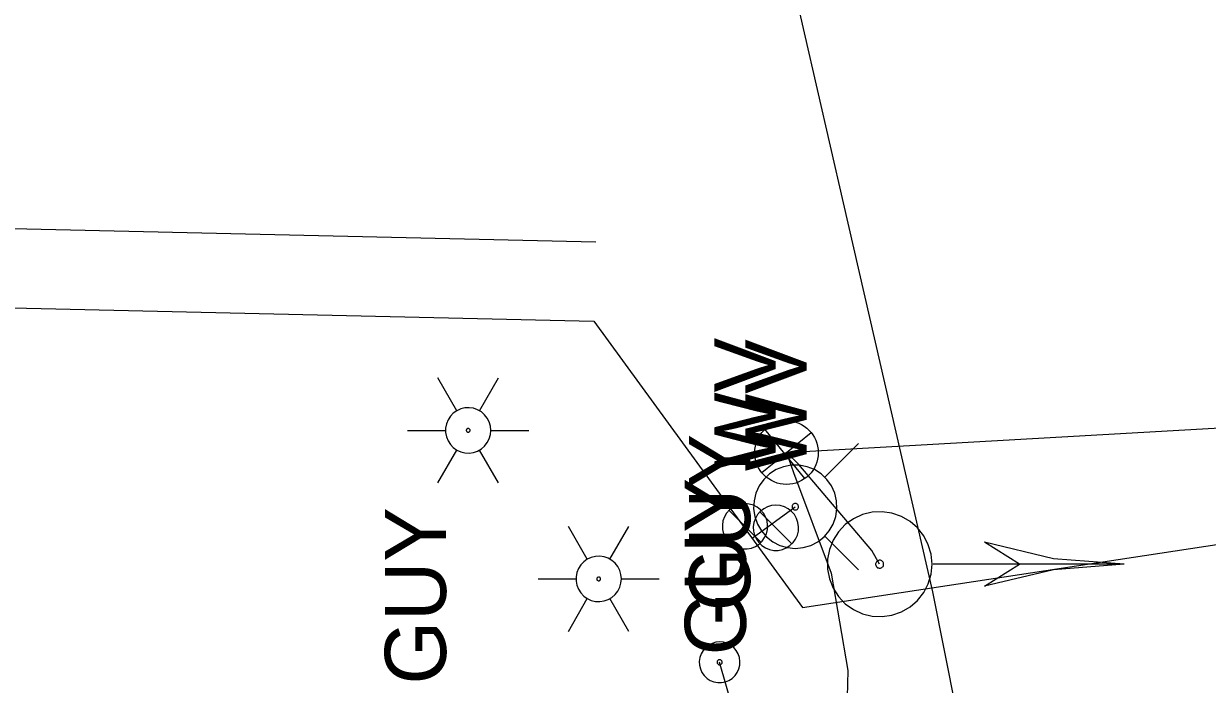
# Model space of a CAD drawing. Extents: x 596028 to 606371, y 330010 to 403088.
# Drawn here: x 604637.5 to 604712, y 339438.6 to 339480.1 of the extents above; entities that cross this region are included whole.
import ezdxf

# ---------------------------------------------------------------- set-up
doc = ezdxf.new("R2010")
doc.units = 0
for name, color, linetype in [('E_LTG', 7, 'Continuous'), ('E_SIG', 7, 'Continuous'), ('E_SIG_Conduit', 7, 'Continuous'), ('E_UTL_E_UG', 7, 'Continuous'), ('E_UTL_EGuyWire', 7, 'Continuous'), ('E_UTL_FO_UG', 7, 'Continuous'), ('E_UTL_G_UG', 7, 'Continuous'), ('E_UTL_W', 7, 'Continuous'), ('E_UTL_W_UG', 7, 'Continuous'), ('E_UTL_WHydrant', 7, 'Continuous')]:
    doc.layers.add(name, color=color, linetype=linetype)

# ---------------------------------------------------------------- blocks, each defined once
blk = doc.blocks.new('_U332')
at = {"layer": 'E_SIG'}
for p, q in [((0, 6.1), (0, -6.1)), ((-6.09, 0.4), (6.1, 0.4))]:
    blk.add_line(p, q, dxfattribs=at)
blk.add_circle((0, 0.01), 6.1, dxfattribs=at)

msp = doc.modelspace()

# ---------------------------------------------------------------- linework, layer by layer
at = {"layer": 'E_LTG'}
for points in [[(604664.786, 339455.777), (604663.595, 339457.839)], [(604666.214, 339455.777), (604667.405, 339457.839)], [(604666.929, 339454.539), (604666.903, 339454.809), (604666.827, 339455.07), (604666.702, 339455.312), (604666.534, 339455.525), (604666.329, 339455.703), (604666.094, 339455.839), (604665.837, 339455.928), (604665.568, 339455.966), (604665.297, 339455.953), (604665.033, 339455.889), (604664.786, 339455.777), (604664.564, 339455.619), (604664.377, 339455.422), (604664.23, 339455.194), (604664.129, 339454.942), (604664.077, 339454.675), (604664.077, 339454.403), (604664.129, 339454.136), (604664.23, 339453.884), (604664.377, 339453.656), (604664.564, 339453.459), (604664.786, 339453.301), (604665.033, 339453.189), (604665.297, 339453.125), (604665.568, 339453.112), (604665.837, 339453.15), (604666.094, 339453.239), (604666.329, 339453.375), (604666.534, 339453.553), (604666.702, 339453.766), (604666.827, 339454.008), (604666.903, 339454.269), (604666.929, 339454.539)], [(604666.929, 339454.539), (604666.903, 339454.809), (604666.827, 339455.07), (604666.702, 339455.312), (604666.534, 339455.525), (604666.329, 339455.703), (604666.094, 339455.839), (604665.837, 339455.928), (604665.568, 339455.966), (604665.297, 339455.953), (604665.033, 339455.889), (604664.786, 339455.777), (604664.564, 339455.619), (604664.377, 339455.422), (604664.23, 339455.194), (604664.129, 339454.942), (604664.077, 339454.675), (604664.077, 339454.403), (604664.129, 339454.136), (604664.23, 339453.884), (604664.377, 339453.656), (604664.564, 339453.459), (604664.786, 339453.301), (604665.033, 339453.189), (604665.297, 339453.125), (604665.568, 339453.112), (604665.837, 339453.15), (604666.094, 339453.239), (604666.329, 339453.375), (604666.534, 339453.553), (604666.702, 339453.766), (604666.827, 339454.008), (604666.903, 339454.269), (604666.929, 339454.539)], [(604666.929, 339454.539), (604666.903, 339454.809), (604666.827, 339455.07), (604666.702, 339455.312), (604666.534, 339455.525), (604666.329, 339455.703), (604666.094, 339455.839), (604665.837, 339455.928), (604665.568, 339455.966), (604665.297, 339455.953), (604665.033, 339455.889), (604664.786, 339455.777), (604664.564, 339455.619), (604664.377, 339455.422), (604664.23, 339455.194), (604664.129, 339454.942), (604664.077, 339454.675), (604664.077, 339454.403), (604664.129, 339454.136), (604664.23, 339453.884), (604664.377, 339453.656), (604664.564, 339453.459), (604664.786, 339453.301), (604665.033, 339453.189), (604665.297, 339453.125), (604665.568, 339453.112), (604665.837, 339453.15), (604666.094, 339453.239), (604666.329, 339453.375), (604666.534, 339453.553), (604666.702, 339453.766), (604666.827, 339454.008), (604666.903, 339454.269), (604666.929, 339454.539)], [(604661.689, 339454.539), (604664.071, 339454.539)], [(604665.619, 339454.539), (604665.617, 339454.562), (604665.611, 339454.583), (604665.6, 339454.603), (604665.586, 339454.621), (604665.569, 339454.636), (604665.549, 339454.647), (604665.528, 339454.655), (604665.506, 339454.658), (604665.483, 339454.657), (604665.461, 339454.652), (604665.44, 339454.642), (604665.422, 339454.629), (604665.406, 339454.613), (604665.394, 339454.594), (604665.386, 339454.573), (604665.381, 339454.55), (604665.381, 339454.528), (604665.386, 339454.505), (604665.394, 339454.484), (604665.406, 339454.465), (604665.422, 339454.449), (604665.44, 339454.436), (604665.461, 339454.426), (604665.483, 339454.421), (604665.506, 339454.42), (604665.528, 339454.423), (604665.549, 339454.431), (604665.569, 339454.442), (604665.586, 339454.457), (604665.6, 339454.475), (604665.611, 339454.495), (604665.617, 339454.516), (604665.619, 339454.539)], [(604666.929, 339454.539), (604669.311, 339454.539)], [(604663.595, 339451.239), (604664.786, 339453.302)], [(604667.405, 339451.239), (604666.214, 339453.302)], [(604672.999, 339446.435), (604671.808, 339448.497)], [(604674.427, 339446.435), (604675.618, 339448.497)], [(604675.142, 339445.197), (604675.116, 339445.467), (604675.04, 339445.728), (604674.915, 339445.97), (604674.747, 339446.183), (604674.542, 339446.361), (604674.307, 339446.497), (604674.05, 339446.586), (604673.781, 339446.624), (604673.51, 339446.611), (604673.246, 339446.547), (604672.999, 339446.435), (604672.777, 339446.277), (604672.59, 339446.08), (604672.443, 339445.852), (604672.342, 339445.6), (604672.29, 339445.333), (604672.29, 339445.061), (604672.342, 339444.794), (604672.443, 339444.542), (604672.59, 339444.314), (604672.777, 339444.117), (604672.999, 339443.959), (604673.246, 339443.847), (604673.51, 339443.783), (604673.781, 339443.77), (604674.05, 339443.808), (604674.307, 339443.897), (604674.542, 339444.033), (604674.747, 339444.211), (604674.915, 339444.424), (604675.04, 339444.666), (604675.116, 339444.927), (604675.142, 339445.197)], [(604675.142, 339445.197), (604675.116, 339445.467), (604675.04, 339445.728), (604674.915, 339445.97), (604674.747, 339446.183), (604674.542, 339446.361), (604674.307, 339446.497), (604674.05, 339446.586), (604673.781, 339446.624), (604673.51, 339446.611), (604673.246, 339446.547), (604672.999, 339446.435), (604672.777, 339446.277), (604672.59, 339446.08), (604672.443, 339445.852), (604672.342, 339445.6), (604672.29, 339445.333), (604672.29, 339445.061), (604672.342, 339444.794), (604672.443, 339444.542), (604672.59, 339444.314), (604672.777, 339444.117), (604672.999, 339443.959), (604673.246, 339443.847), (604673.51, 339443.783), (604673.781, 339443.77), (604674.05, 339443.808), (604674.307, 339443.897), (604674.542, 339444.033), (604674.747, 339444.211), (604674.915, 339444.424), (604675.04, 339444.666), (604675.116, 339444.927), (604675.142, 339445.197)], [(604675.142, 339445.197), (604675.116, 339445.467), (604675.04, 339445.728), (604674.915, 339445.97), (604674.747, 339446.183), (604674.542, 339446.361), (604674.307, 339446.497), (604674.05, 339446.586), (604673.781, 339446.624), (604673.51, 339446.611), (604673.246, 339446.547), (604672.999, 339446.435), (604672.777, 339446.277), (604672.59, 339446.08), (604672.443, 339445.852), (604672.342, 339445.6), (604672.29, 339445.333), (604672.29, 339445.061), (604672.342, 339444.794), (604672.443, 339444.542), (604672.59, 339444.314), (604672.777, 339444.117), (604672.999, 339443.959), (604673.246, 339443.847), (604673.51, 339443.783), (604673.781, 339443.77), (604674.05, 339443.808), (604674.307, 339443.897), (604674.542, 339444.033), (604674.747, 339444.211), (604674.915, 339444.424), (604675.04, 339444.666), (604675.116, 339444.927), (604675.142, 339445.197)], [(604669.902, 339445.197), (604672.284, 339445.197)], [(604673.832, 339445.197), (604673.83, 339445.22), (604673.824, 339445.241), (604673.813, 339445.261), (604673.799, 339445.279), (604673.782, 339445.294), (604673.762, 339445.305), (604673.741, 339445.313), (604673.719, 339445.316), (604673.696, 339445.315), (604673.674, 339445.31), (604673.653, 339445.3), (604673.635, 339445.287), (604673.619, 339445.271), (604673.607, 339445.252), (604673.599, 339445.231), (604673.594, 339445.208), (604673.594, 339445.186), (604673.599, 339445.163), (604673.607, 339445.142), (604673.619, 339445.123), (604673.635, 339445.107), (604673.653, 339445.094), (604673.674, 339445.084), (604673.696, 339445.079), (604673.719, 339445.078), (604673.741, 339445.081), (604673.762, 339445.089), (604673.782, 339445.1), (604673.799, 339445.115), (604673.813, 339445.133), (604673.824, 339445.153), (604673.83, 339445.174), (604673.832, 339445.197)], [(604675.142, 339445.197), (604677.524, 339445.197)], [(604671.808, 339441.897), (604672.999, 339443.96)], [(604675.618, 339441.897), (604674.427, 339443.96)]]:
    msp.add_lwpolyline(points, dxfattribs=at)
at = {"layer": 'E_SIG'}
for points in [[(604691.401, 339446.121), (604690.901, 339446.981), (604686.321, 339452.391), (604685.541, 339453.141)], [(604694.701, 339446.121), (604694.642, 339446.745), (604694.465, 339447.347), (604694.178, 339447.905), (604693.79, 339448.398), (604693.316, 339448.809), (604692.772, 339449.122), (604692.179, 339449.328), (604691.558, 339449.417), (604690.932, 339449.387), (604690.322, 339449.239), (604689.751, 339448.978), (604689.24, 339448.615), (604688.807, 339448.161), (604688.468, 339447.633), (604688.235, 339447.05), (604688.116, 339446.434), (604688.116, 339445.807), (604688.235, 339445.191), (604688.468, 339444.608), (604688.807, 339444.081), (604689.24, 339443.627), (604689.751, 339443.263), (604690.322, 339443.002), (604690.932, 339442.854), (604691.558, 339442.824), (604692.179, 339442.914), (604692.772, 339443.119), (604693.316, 339443.433), (604693.79, 339443.843), (604694.178, 339444.336), (604694.465, 339444.894), (604694.642, 339445.496), (604694.701, 339446.121)], [(604706.801, 339446.121), (604702.348, 339446.466), (604698.001, 339447.496)], [(604700.202, 339446.119), (604698.002, 339447.496)], [(604691.654, 339446.121), (604691.649, 339446.168), (604691.636, 339446.214), (604691.614, 339446.257), (604691.584, 339446.295), (604691.548, 339446.326), (604691.506, 339446.35), (604691.461, 339446.366), (604691.413, 339446.373), (604691.365, 339446.37), (604691.319, 339446.359), (604691.275, 339446.339), (604691.236, 339446.311), (604691.203, 339446.277), (604691.177, 339446.236), (604691.159, 339446.192), (604691.15, 339446.145), (604691.15, 339446.097), (604691.159, 339446.05), (604691.177, 339446.005), (604691.203, 339445.965), (604691.236, 339445.93), (604691.275, 339445.902), (604691.319, 339445.882), (604691.365, 339445.871), (604691.413, 339445.868), (604691.461, 339445.875), (604691.506, 339445.891), (604691.548, 339445.915), (604691.584, 339445.946), (604691.614, 339445.984), (604691.636, 339446.027), (604691.649, 339446.073), (604691.654, 339446.121)], [(604706.801, 339446.119), (604694.76, 339446.119)], [(604706.801, 339446.121), (604702.348, 339445.775), (604698.001, 339444.746)], [(604698.002, 339444.748), (604700.202, 339446.119)]]:
    msp.add_lwpolyline(points, dxfattribs=at)
at = {"layer": 'E_SIG_Conduit'}
for points in [[(604685.541, 339453.141), (604748.601, 339456.731)], [(604685.541, 339453.141), (604685.981, 339451.881), (604688.351, 339445.561), (604689.391, 339439.431), (604689.301, 339435.251), (604688.651, 339432.791)]]:
    msp.add_lwpolyline(points, dxfattribs=at)
at = {"layer": 'E_UTL_E_UG'}
msp.add_line((604541.191, 339469.419), (604673.529, 339466.399), dxfattribs=at)
at = {"layer": 'E_UTL_EGuyWire'}
msp.add_line((604683.979, 339430.78), (604681.327, 339439.949), dxfattribs=at)
for points in [[(604681.327, 339441.232), (604681.084, 339441.209), (604680.85, 339441.14), (604680.633, 339441.029), (604680.441, 339440.878), (604680.282, 339440.693), (604680.16, 339440.482), (604680.08, 339440.252), (604680.045, 339440.01), (604680.057, 339439.766), (604680.114, 339439.529), (604680.216, 339439.307), (604680.357, 339439.109), (604680.534, 339438.94), (604680.739, 339438.808), (604680.965, 339438.718), (604681.205, 339438.671), (604681.449, 339438.671), (604681.689, 339438.718), (604681.915, 339438.808), (604682.12, 339438.94), (604682.297, 339439.109), (604682.438, 339439.307), (604682.54, 339439.529), (604682.597, 339439.766), (604682.609, 339440.01), (604682.574, 339440.252), (604682.494, 339440.482), (604682.372, 339440.693), (604682.213, 339440.878), (604682.021, 339441.029), (604681.804, 339441.14), (604681.57, 339441.209), (604681.327, 339441.232)], [(604681.327, 339440.109), (604681.297, 339440.107), (604681.267, 339440.098), (604681.24, 339440.084), (604681.216, 339440.065), (604681.196, 339440.042), (604681.181, 339440.016), (604681.171, 339439.987), (604681.167, 339439.957), (604681.168, 339439.926), (604681.175, 339439.897), (604681.188, 339439.869), (604681.206, 339439.844), (604681.228, 339439.823), (604681.253, 339439.806), (604681.282, 339439.795), (604681.312, 339439.789), (604681.342, 339439.789), (604681.372, 339439.795), (604681.401, 339439.806), (604681.426, 339439.823), (604681.448, 339439.844), (604681.466, 339439.869), (604681.479, 339439.897), (604681.486, 339439.926), (604681.487, 339439.957), (604681.483, 339439.987), (604681.473, 339440.016), (604681.458, 339440.042), (604681.438, 339440.065), (604681.414, 339440.084), (604681.387, 339440.098), (604681.357, 339440.107), (604681.327, 339440.109)]]:
    msp.add_lwpolyline(points, dxfattribs=at)
at = {"layer": 'E_UTL_FO_UG'}
msp.add_lwpolyline([(604685.541, 339453.141), (604748.601, 339456.731), (604793.27, 339456.481)], dxfattribs=at)
at = {"layer": 'E_UTL_G_UG'}
msp.add_lwpolyline([(604742.351, 339228.682), (604740.051, 339238.172), (604732.171, 339281.151), (604723.131, 339319.311), (604718.151, 339342.271), (604709.951, 339377.231), (604705.891, 339396.141), (604699.951, 339418.231), (604694.751, 339444.391), (604689.121, 339468.851), (604685.031, 339486.701), (604684.681, 339487.291), (604678.371, 339490.441), (604676.201, 339500.021)], dxfattribs=at)
at = {"layer": 'E_UTL_W'}
for points in [[(604682.926, 339449.929), (604682.656, 339449.903), (604682.396, 339449.827), (604682.155, 339449.703), (604681.942, 339449.535), (604681.764, 339449.33), (604681.629, 339449.095), (604681.54, 339448.839), (604681.501, 339448.571), (604681.514, 339448.3), (604681.578, 339448.037), (604681.691, 339447.79), (604681.848, 339447.569), (604682.044, 339447.382), (604682.272, 339447.236), (604682.524, 339447.135), (604682.79, 339447.084), (604683.061, 339447.084), (604683.328, 339447.135), (604683.579, 339447.236), (604683.807, 339447.382), (604684.003, 339447.569), (604684.161, 339447.79), (604684.273, 339448.037), (604684.337, 339448.3), (604684.35, 339448.571), (604684.312, 339448.839), (604684.223, 339449.095), (604684.087, 339449.33), (604683.91, 339449.535), (604683.697, 339449.703), (604683.456, 339449.827), (604683.196, 339449.903), (604682.926, 339449.929)], [(604683.934, 339447.495), (604681.918, 339449.511)], [(604684.874, 339449.836), (604684.604, 339449.81), (604684.344, 339449.733), (604684.103, 339449.609), (604683.89, 339449.442), (604683.712, 339449.237), (604683.577, 339449.002), (604683.488, 339448.746), (604683.45, 339448.478), (604683.462, 339448.207), (604683.526, 339447.943), (604683.639, 339447.697), (604683.796, 339447.476), (604683.992, 339447.289), (604684.22, 339447.142), (604684.472, 339447.041), (604684.738, 339446.99), (604685.009, 339446.99), (604685.276, 339447.041), (604685.527, 339447.142), (604685.755, 339447.289), (604685.952, 339447.476), (604686.109, 339447.697), (604686.221, 339447.943), (604686.285, 339448.207), (604686.298, 339448.478), (604686.26, 339448.746), (604686.171, 339449.002), (604686.035, 339449.237), (604685.858, 339449.442), (604685.645, 339449.609), (604685.404, 339449.733), (604685.144, 339449.81), (604684.874, 339449.836)], [(604685.882, 339447.401), (604683.866, 339449.418)]]:
    msp.add_lwpolyline(points, dxfattribs=at)
at = {"layer": 'E_UTL_W_UG'}
for p, q in [((604536.91, 339464.515), (604673.415, 339461.4)), ((604683.369, 339447.751), (604686.091, 339449.736))]:
    msp.add_line(p, q, dxfattribs=at)
msp.add_lwpolyline([(604673.415, 339461.4), (604686.537, 339443.406), (604745.201, 339452.301), (604755.11, 339453.801), (604801.174, 339464.209)], dxfattribs=at)
at = {"layer": 'E_UTL_WHydrant'}
for points in [[(604687.926, 339451.57), (604690.068, 339453.713)], [(604686.091, 339447.113), (604686.587, 339447.161), (604687.066, 339447.301), (604687.509, 339447.53), (604687.901, 339447.838), (604688.227, 339448.215), (604688.477, 339448.646), (604688.64, 339449.118), (604688.711, 339449.611), (604688.687, 339450.109), (604688.57, 339450.594), (604688.362, 339451.047), (604688.073, 339451.454), (604687.712, 339451.798), (604687.293, 339452.067), (604686.83, 339452.253), (604686.34, 339452.347), (604685.842, 339452.347), (604685.352, 339452.253), (604684.889, 339452.067), (604684.47, 339451.798), (604684.109, 339451.454), (604683.82, 339451.047), (604683.612, 339450.594), (604683.495, 339450.109), (604683.471, 339449.611), (604683.542, 339449.118), (604683.705, 339448.646), (604683.955, 339448.215), (604684.281, 339447.838), (604684.673, 339447.53), (604685.116, 339447.301), (604685.595, 339447.161), (604686.091, 339447.113)], [(604686.091, 339449.535), (604686.129, 339449.539), (604686.166, 339449.55), (604686.199, 339449.567), (604686.229, 339449.591), (604686.254, 339449.62), (604686.273, 339449.653), (604686.286, 339449.689), (604686.291, 339449.726), (604686.29, 339449.765), (604686.281, 339449.802), (604686.265, 339449.836), (604686.243, 339449.867), (604686.215, 339449.894), (604686.183, 339449.914), (604686.148, 339449.928), (604686.11, 339449.936), (604686.072, 339449.936), (604686.034, 339449.928), (604685.999, 339449.914), (604685.967, 339449.894), (604685.939, 339449.867), (604685.917, 339449.836), (604685.901, 339449.802), (604685.892, 339449.765), (604685.891, 339449.726), (604685.896, 339449.689), (604685.909, 339449.653), (604685.928, 339449.62), (604685.953, 339449.591), (604685.983, 339449.567), (604686.016, 339449.55), (604686.053, 339449.539), (604686.091, 339449.535)], [(604687.926, 339447.9), (604690.068, 339445.758)]]:
    msp.add_lwpolyline(points, dxfattribs=at)

# ---------------------------------------------------------------- block references
at = {"layer": 'E_SIG_Conduit', "xscale": 0.32808333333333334, "yscale": 0.3280833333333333, "rotation": 128.98470111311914}
msp.add_blockref('_U332', (604685.541, 339453.141), dxfattribs=at)

# ---------------------------------------------------------------- texts
at = {"layer": 'E_UTL_EGuyWire'}
for p in [(604683.252, 339443.157), (604682.985, 339440.384), (604664.105, 339438.551)]:
    msp.add_text('GUY', height=3.85, rotation=90, dxfattribs=at).set_placement(p)
at = {"layer": 'E_UTL_W'}
for p in [(604684.851, 339452.068), (604686.799, 339451.974)]:
    msp.add_text('WV', height=3.85, rotation=90, dxfattribs=at).set_placement(p)

doc.saveas('drawing.dxf')
